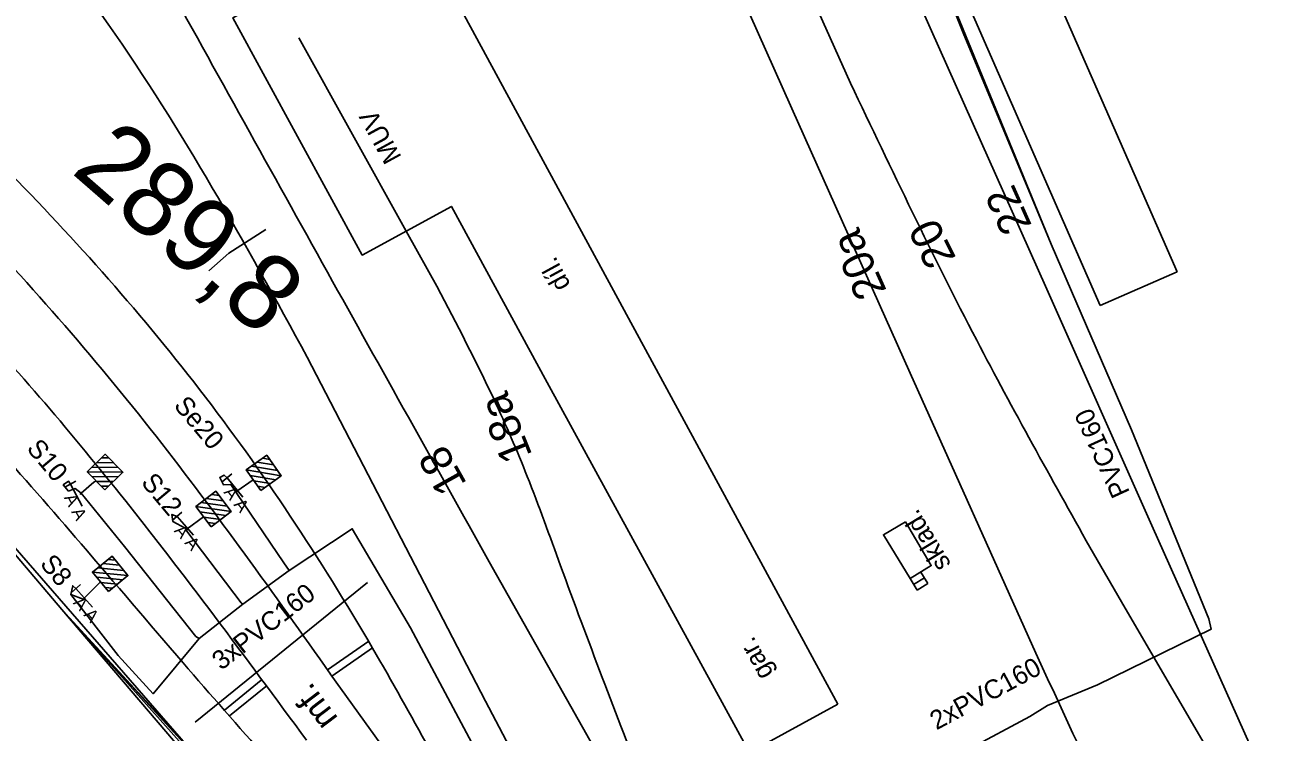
# Model space of a CAD drawing. Extents: x -496570 to -495506, y -1089156 to -1088046.
# Drawn here: x -496096.7 to -495998.4, y -1088485 to -1088429 of the extents above; entities that cross this region are included whole.
import ezdxf

# ---------------------------------------------------------------- set-up
doc = ezdxf.new("R2010")
doc.units = 0
for name, color, linetype in [('11', 7, 'Continuous'), ('14', 7, 'Continuous'), ('15', 7, 'Continuous'), ('20', 7, 'Continuous'), ('39', 7, 'Continuous'), ('54', 7, 'Continuous'), ('PŘÍSTUPOVÉ_CESTY', 7, 'Continuous'), ('PŮVODNÍ_NÁVRH', 7, 'Continuous'), ('SEE', 7, 'Continuous')]:
    doc.layers.add(name, color=color, linetype=linetype)

msp = doc.modelspace()

# ---------------------------------------------------------------- linework, layer by layer
at = {"layer": '11'}
for p, q in [((-496072.683, -1088480.056), (-496069.413, -1088477.787)), ((-496072.333, -1088480.543), (-496069.122, -1088478.315)), ((-496080.847, -1088483.255), (-496077.937, -1088480.885)), ((-496080.452, -1088483.707), (-496077.574, -1088481.363))]:
    msp.add_line(p, q, dxfattribs=at)
at = {"layer": '14'}
for points in [[(-496031.216, -1088433.587), (-496042.641, -1088408.12), (-496063.79, -1088360.598), (-496069.753, -1088347.338)], [(-496016.532, -1088478.726), (-496026.498, -1088456.559), (-496035.879, -1088435.575), (-496046.648, -1088411.427), (-496055.896, -1088390.674), (-496071.432, -1088355.64)], [(-495984.212, -1088520.604), (-495987.937, -1088512.179), (-495995.163, -1088495.835), (-496007.326, -1088468.627), (-496015.768, -1088449.655), (-496024.81, -1088429.42), (-496048.198, -1088376.798)], [(-496066.446, -1088445.295), (-496074.946, -1088429.986)], [(-496063.891, -1088449.907), (-496066.446, -1088445.295)], [(-496029.461, -1088539.924), (-496035.456, -1088528.788), (-496050.622, -1088500.683), (-496060.148, -1088482.537), (-496074.283, -1088455.273)], [(-495987.937, -1088512.179), (-495997.014, -1088496.474), (-496009.447, -1088475.159), (-496012.25, -1088470.334)], [(-496027.558, -1088528.593), (-496035.765, -1088514.119), (-496040.307, -1088506.105), (-496049.124, -1088490.548), (-496059.857, -1088471.5)], [(-496011.29, -1088565.037), (-496022.068, -1088550.141), (-496029.461, -1088539.924), (-496036.884, -1088529.665), (-496046.952, -1088515.759), (-496054.33, -1088505.532), (-496061.713, -1088495.299), (-496072.458, -1088480.37)]]:
    msp.add_lwpolyline(points, dxfattribs=at)
for points in [[(-496074.283, -1088455.273), (-496090.055, -1088428.91), (-496108.418, -1088407.261), (-496129.685, -1088387.877)], [(-496060.305, -1088494.392), (-496069.107, -1088478.342), (-496082.819, -1088457.845), (-496098.833, -1088439.695), (-496101.304, -1088437.234), (-496120.979, -1088419.513)], [(-496072.447, -1088480.385), (-496086.263, -1088461.553), (-496102.223, -1088443.302), (-496125.575, -1088421.675)], [(-496059.857, -1088471.5), (-496072.678, -1088448.56), (-496085.881, -1088424.782)], [(-496074.345, -1088485.622), (-496089.123, -1088466.132), (-496102.218, -1088451.049), (-496125.082, -1088429.936)], [(-496077.528, -1088487.052), (-496084.13, -1088479.499), (-496092.21, -1088470.077), (-496106.458, -1088454.308), (-496128.434, -1088433.508)], [(-496012.25, -1088470.334), (-496021.218, -1088453.942), (-496031.216, -1088433.587)], [(-496047.516, -1088489.457), (-496054.207, -1088471.811), (-496056.848, -1088464.728), (-496059.479, -1088458.647), (-496063.984, -1088449.723)], [(-495998.352, -1088515.291), (-496007.808, -1088497.191), (-496016.532, -1088478.726)]]:
    msp.add_spline(points, degree=3, dxfattribs=at)
at = {"layer": '15'}
for p, q in [((-496089.269, -1088464.021), (-496091.348, -1088463.994)), ((-496089.64, -1088463.641), (-496090.968, -1088463.623)), ((-496090.009, -1088463.261), (-496090.588, -1088463.254)), ((-496076.649, -1088464.251), (-496078.699, -1088463.908)), ((-496076.957, -1088463.819), (-496078.267, -1088463.6)), ((-496077.265, -1088463.388), (-496077.835, -1088463.292)), ((-496088.899, -1088464.401), (-496091.728, -1088464.364)), ((-496089.279, -1088464.771), (-496091.358, -1088464.743)), ((-496076.341, -1088464.683), (-496079.131, -1088464.216)), ((-496076.773, -1088464.991), (-496078.823, -1088464.647)), ((-496089.66, -1088465.141), (-496090.987, -1088465.124)), ((-496090.039, -1088465.511), (-496090.618, -1088465.503)), ((-496077.205, -1088465.299), (-496078.515, -1088465.08)), ((-496077.636, -1088465.607), (-496078.207, -1088465.511)), ((-496080.635, -1088467.081), (-496082.695, -1088466.803)), ((-496080.957, -1088466.659), (-496082.273, -1088466.481)), ((-496081.278, -1088466.237), (-496081.851, -1088466.16)), ((-496080.313, -1088467.503), (-496083.116, -1088467.125)), ((-496080.735, -1088467.824), (-496082.795, -1088467.546)), ((-496081.157, -1088468.146), (-496082.473, -1088467.969)), ((-496081.578, -1088468.467), (-496082.152, -1088468.39)), ((-496089.168, -1088471.77), (-496090.489, -1088471.635)), ((-496089.502, -1088471.359), (-496090.078, -1088471.3)), ((-496088.498, -1088472.592), (-496091.311, -1088472.305)), ((-496088.909, -1088472.927), (-496090.977, -1088472.716)), ((-496088.832, -1088472.181), (-496090.901, -1088471.97)), ((-496089.32, -1088473.262), (-496090.641, -1088473.127)), ((-496089.731, -1088473.597), (-496090.307, -1088473.538))]:
    msp.add_line(p, q, dxfattribs=at)
for points in [[(-496090.332, -1088465.796), (-496091.728, -1088464.364), (-496090.295, -1088462.968), (-496088.899, -1088464.401)], [(-496090.332, -1088465.796), (-496091.728, -1088464.364), (-496090.295, -1088462.968), (-496088.899, -1088464.401)], [(-496077.969, -1088465.844), (-496079.131, -1088464.216), (-496077.502, -1088463.055), (-496076.341, -1088464.683)], [(-496077.969, -1088465.844), (-496079.131, -1088464.216), (-496077.502, -1088463.055), (-496076.341, -1088464.683)], [(-496081.904, -1088468.715), (-496083.116, -1088467.125), (-496081.526, -1088465.912), (-496080.313, -1088467.503)], [(-496081.904, -1088468.715), (-496083.116, -1088467.125), (-496081.526, -1088465.912), (-496080.313, -1088467.503)], [(-496090.049, -1088473.855), (-496091.311, -1088472.305), (-496089.761, -1088471.042), (-496088.498, -1088472.592)], [(-496090.049, -1088473.855), (-496091.311, -1088472.305), (-496089.761, -1088471.042), (-496088.498, -1088472.592)]]:
    msp.add_lwpolyline(points, close=True, dxfattribs=at)
for points in [[(-496090.332, -1088465.796), (-496091.728, -1088464.364), (-496090.295, -1088462.968), (-496088.899, -1088464.401), (-496090.332, -1088465.796)], [(-496090.332, -1088465.796), (-496091.728, -1088464.364), (-496090.295, -1088462.968), (-496088.899, -1088464.401), (-496090.332, -1088465.796)], [(-496077.969, -1088465.844), (-496079.131, -1088464.216), (-496077.502, -1088463.055), (-496076.341, -1088464.683), (-496077.969, -1088465.844)], [(-496077.969, -1088465.844), (-496079.131, -1088464.216), (-496077.502, -1088463.055), (-496076.341, -1088464.683), (-496077.969, -1088465.844)], [(-496081.904, -1088468.715), (-496083.116, -1088467.125), (-496081.526, -1088465.912), (-496080.313, -1088467.503), (-496081.904, -1088468.715)], [(-496081.904, -1088468.715), (-496083.116, -1088467.125), (-496081.526, -1088465.912), (-496080.313, -1088467.503), (-496081.904, -1088468.715)], [(-496090.049, -1088473.855), (-496091.311, -1088472.305), (-496089.761, -1088471.042), (-496088.498, -1088472.592), (-496090.049, -1088473.855)], [(-496090.049, -1088473.855), (-496091.311, -1088472.305), (-496089.761, -1088471.042), (-496088.498, -1088472.592), (-496090.049, -1088473.855)]]:
    msp.add_lwpolyline(points, dxfattribs=at)
at = {"layer": '20'}
for p, q in [((-496080.256, -1088464.536), (-496081.032, -1088465.166)), ((-496079.395, -1088466.387), (-496080.644, -1088464.851)), ((-496092.619, -1088465.107), (-496093.503, -1088465.573)), ((-496092.138, -1088467.092), (-496093.061, -1088465.34)), ((-496084.233, -1088467.571), (-496084.987, -1088468.229)), ((-496083.307, -1088469.391), (-496084.61, -1088467.9)), ((-496092.259, -1088473.282), (-496093.005, -1088473.948)), ((-496091.314, -1088475.092), (-496092.632, -1088473.615))]:
    msp.add_line(p, q, dxfattribs=at)
at = {"layer": '39'}
for p, q in [((-496005.336, -1088448.518), (-496031.21, -1088389.46)), ((-496005.336, -1088448.518), (-496011.44, -1088451.19)), ((-496025.943, -1088473.741), (-496026.499, -1088472.827)), ((-496025.367, -1088472.763), (-496026.222, -1088473.282)), ((-496025.645, -1088472.307), (-496025.088, -1088473.221)), ((-496025.088, -1088473.221), (-496025.943, -1088473.741))]:
    msp.add_line(p, q, dxfattribs=at)
for points in [[(-496031.21, -1088389.46), (-496031.7, -1088389.65), (-496039.78, -1088371.31), (-496045.35, -1088373.79), (-496011.44, -1088451.19)], [(-496032.231, -1088482.763), (-496039.242, -1088486.597), (-496055.259, -1088457.292), (-496062.86, -1088443.337), (-496069.929, -1088447.197), (-496080.182, -1088428.388), (-496065.919, -1088420.663), (-496032.231, -1088482.763)], [(-496026.87, -1088468.328), (-496024.827, -1088471.796), (-496026.499, -1088472.827), (-496028.613, -1088469.355), (-496026.87, -1088468.328)]]:
    msp.add_lwpolyline(points, dxfattribs=at)
at = {"layer": '54'}
msp.add_line((-496092.21, -1088466.05), (-496092.29, -1088466.17), dxfattribs=at)
for points in [[(-496035.05, -1088546.1), (-496051.31, -1088524.79), (-496051.95, -1088524), (-496075.46, -1088495.01), (-496082.21, -1088487.56), (-496083.74, -1088486.13), (-496115.78, -1088449.34), (-496116.666, -1088448.476), (-496129.8, -1088436.28), (-496168.994, -1088401.872), (-496172.14, -1088399.257), (-496208.919, -1088366.316), (-496218.168, -1088358.05), (-496219.89, -1088357.07), (-496221.818, -1088357.316), (-496227.949, -1088364.044), (-496231.283, -1088367.587), (-496235.293, -1088372.311), (-496239.162, -1088376.183), (-496245.965, -1088384.343), (-496248.182, -1088386.654), (-496249.196, -1088385.882), (-496252.528, -1088385.701), (-496270.673, -1088369.666)], [(-496249.196, -1088385.882), (-496248.182, -1088386.654), (-496245.965, -1088384.343), (-496239.162, -1088376.183), (-496235.293, -1088372.311), (-496231.283, -1088367.587), (-496227.949, -1088364.044), (-496221.818, -1088357.316), (-496219.9, -1088357.08), (-496218.168, -1088358.05), (-496208.919, -1088366.316), (-496172.14, -1088399.257), (-496168.994, -1088401.872), (-496129.8, -1088436.28), (-496116.666, -1088448.476), (-496115.78, -1088449.34), (-496093.74, -1088475.27), (-496082.49, -1088487.89), (-496075.35, -1088495.41), (-496051.95, -1088524), (-496051.31, -1088524.79), (-496034.93, -1088546.87)], [(-496035.05, -1088546.1), (-496051.01, -1088524.68), (-496051.95, -1088524), (-496075.35, -1088495.41), (-496082.21, -1088487.56), (-496083.74, -1088486.13), (-496093.74, -1088475.27), (-496115.78, -1088449.34)], [(-496075.731, -1088472.172), (-496076.141, -1088471.584), (-496079.88, -1088466.08), (-496080.342, -1088465.38), (-496080.912, -1088465.406), (-496081.219, -1088464.806), (-496080.859, -1088464.63), (-496080.644, -1088464.851)], [(-496082.858, -1088477.58), (-496083.108, -1088477.421), (-496088.76, -1088470.29), (-496092.21, -1088466.05), (-496092.685, -1088465.695), (-496093.2, -1088465.889), (-496093.626, -1088465.402), (-496093.222, -1088465.097), (-496093.061, -1088465.34)], [(-496092.21, -1088466.05), (-496091.21, -1088465.19), (-496091.03, -1088465.08)], [(-496079.88, -1088466.08), (-496079.89, -1088465.99), (-496079.8, -1088465.85), (-496078.66, -1088465.05), (-496078.55, -1088465.03)], [(-496079.383, -1088474.861), (-496079.52, -1088474.74), (-496083.82, -1088469.06), (-496083.97, -1088468.82), (-496084.93, -1088468.31), (-496085.02, -1088467.74), (-496084.61, -1088467.9)], [(-496083.82, -1088469.06), (-496083.81, -1088468.88), (-496082.51, -1088467.92)], [(-496092.632, -1088473.615), (-496092.88, -1088473.387), (-496093.03, -1088474.095), (-496089.266, -1088478.913), (-496086.51, -1088481.943), (-496082.858, -1088477.58), (-496079.383, -1088474.861), (-496075.731, -1088472.172), (-496070.715, -1088468.877), (-496066.112, -1088476.72), (-496059.764, -1088488.605), (-496056.52, -1088494.969), (-496054.901, -1088498.484), (-496054.771, -1088498.702), (-496054.01, -1088499.84), (-496052.4, -1088499.06)], [(-496090.68, -1088473.08), (-496092.06, -1088474.46), (-496093.03, -1088474.095)]]:
    msp.add_lwpolyline(points, dxfattribs=at)
at = {"layer": 'PŮVODNÍ_NÁVRH'}
msp.add_line((-496083.18, -1088484.21), (-496069.52, -1088473.14), dxfattribs=at)
for points in [[(-496002.63, -1088476.82), (-496002.82, -1088476.02), (-496008.96, -1088461.03), (-496015.33, -1088446.34), (-496022.3, -1088429.58), (-496027.34, -1088417), (-496033.98, -1088400.73), (-496038.24, -1088391.07)], [(-496082.1, -1088448.43), (-496080.51, -1088447.04), (-496077.56, -1088445.16)], [(-496015.829, -1088567.72), (-496024.83, -1088557.73), (-496034.93, -1088546.87), (-496051.31, -1088524.79), (-496051.95, -1088524), (-496075.35, -1088495.41), (-496082.21, -1088487.56), (-496083.78, -1088486.19), (-496093.74, -1088475.27), (-496115.78, -1088449.34)], [(-496086.51, -1088481.943), (-496082.858, -1088477.58), (-496079.383, -1088474.861), (-496075.731, -1088472.172), (-496070.715, -1088468.877)], [(-496046.99, -1088501.65), (-496042.82, -1088499.36), (-496035.34, -1088494.54), (-496026.68, -1088488.94), (-496017.01, -1088483.74), (-496015.61, -1088482.89), (-496011.64, -1088481.25), (-496002.63, -1088476.82)]]:
    msp.add_lwpolyline(points, dxfattribs=at)
at = {"layer": 'SEE'}
for points in [[(-496051.62, -1088524.39), (-496051.01, -1088524.72), (-496048.89, -1088527.16), (-496044.09, -1088523.58), (-496040.8, -1088521.19), (-496037.7, -1088519.67), (-496041.89, -1088512.27), (-496046.41, -1088504), (-496046.99, -1088501.65), (-496042.82, -1088499.36), (-496035.34, -1088494.54), (-496026.68, -1088488.94), (-496017.01, -1088483.74), (-496015.61, -1088482.89), (-496011.64, -1088481.25), (-496002.63, -1088476.82), (-496002.82, -1088476.02), (-496008.96, -1088461.03), (-496015.33, -1088446.34), (-496027.34, -1088417), (-496033.98, -1088400.73), (-496038.24, -1088391.07)], [(-496115.78, -1088449.34), (-496093.74, -1088475.27), (-496084.13, -1088486.54), (-496082.5, -1088487.93), (-496075.35, -1088495.41), (-496051.95, -1088524), (-496051.31, -1088524.79), (-496034.93, -1088546.87)], [(-496115.78, -1088449.34), (-496093.74, -1088475.27), (-496084.13, -1088486.54), (-496082.5, -1088487.93), (-496075.35, -1088495.41), (-496051.95, -1088524), (-496051.31, -1088524.79), (-496034.93, -1088546.87)]]:
    msp.add_lwpolyline(points, dxfattribs=at)

# ---------------------------------------------------------------- texts
at = {"layer": '11'}
msp.add_text('289,8', height=6, rotation=318.94379, dxfattribs=at).set_placement((-496093.091, -1088440.616))
at = {"layer": '14'}
for s, rotation, p in [('22', 114.07746, (-496016.817, -1088444.857)), ('20a', 114.08726, (-496028.329, -1088450.014)), ('20', 116.28024, (-496022.822, -1088447.44)), ('18a', 111.64119, (-496056.425, -1088463.05)), ('18', 119.22479, (-496061.595, -1088465.319))]:
    msp.add_text(s, height=2.5, rotation=rotation, dxfattribs=at).set_placement(p)
at = {"layer": '20'}
for s, height, rotation, p in [('Se20', 1.5, 310, (-496084.928, -1088459.15)), ('S10', 1.5, 310, (-496096.593, -1088462.552)), ('S12', 1.5, 310, (-496087.52, -1088465.243)), ('  A A', 1, 309.12096, (-496081.427, -1088465.432)), ('  A A', 1, 297.7771, (-496093.943, -1088465.756)), ('  A A', 1, 311.13518, (-496085.372, -1088468.508)), ('S8', 1.5, 310, (-496095.538, -1088471.686)), ('  A A', 1, 311.74551, (-496093.387, -1088474.231))]:
    msp.add_text(s, height=height, rotation=rotation, dxfattribs=at).set_placement(p)
at = {"layer": '39'}
for s, rotation, p in [('MUV', 118.5953, (-496066.774, -1088439.432)), ('díl.', 118.57622, (-496053.372, -1088449.558)), ('sklad.', 121.33602, (-496023.214, -1088471.679)), ('gar.', 118.65934, (-496037.295, -1088480.335))]:
    msp.add_text(s, height=1.5, rotation=rotation, dxfattribs=at).set_placement(p)
at = {"layer": '54'}
msp.add_text('3xPVC160', height=1.5, rotation=37.67656, dxfattribs=at).set_placement((-496081.101, -1088480.142))
at = {"layer": 'PŘÍSTUPOVÉ_CESTY'}
msp.add_text('mf.', height=2, rotation=127.16284, dxfattribs=at).set_placement((-496071.792, -1088483.894))
at = {"layer": 'SEE'}
for s, rotation, p in [('PVC160', 114.53809, (-496009.056, -1088465.992)), ('2xPVC160', 28.26372, (-496024.411, -1088484.856))]:
    msp.add_text(s, height=1.5, rotation=rotation, dxfattribs=at).set_placement(p)

doc.saveas('drawing.dxf')
